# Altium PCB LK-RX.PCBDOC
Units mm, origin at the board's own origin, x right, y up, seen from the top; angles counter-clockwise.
Board outline 26.25 x 26.26 mm, 4 copper layers (Top Layer, MidLayer1, MidLayer2, Bottom Layer); 71 components, 48 nets, 217 pads, 64 vias.
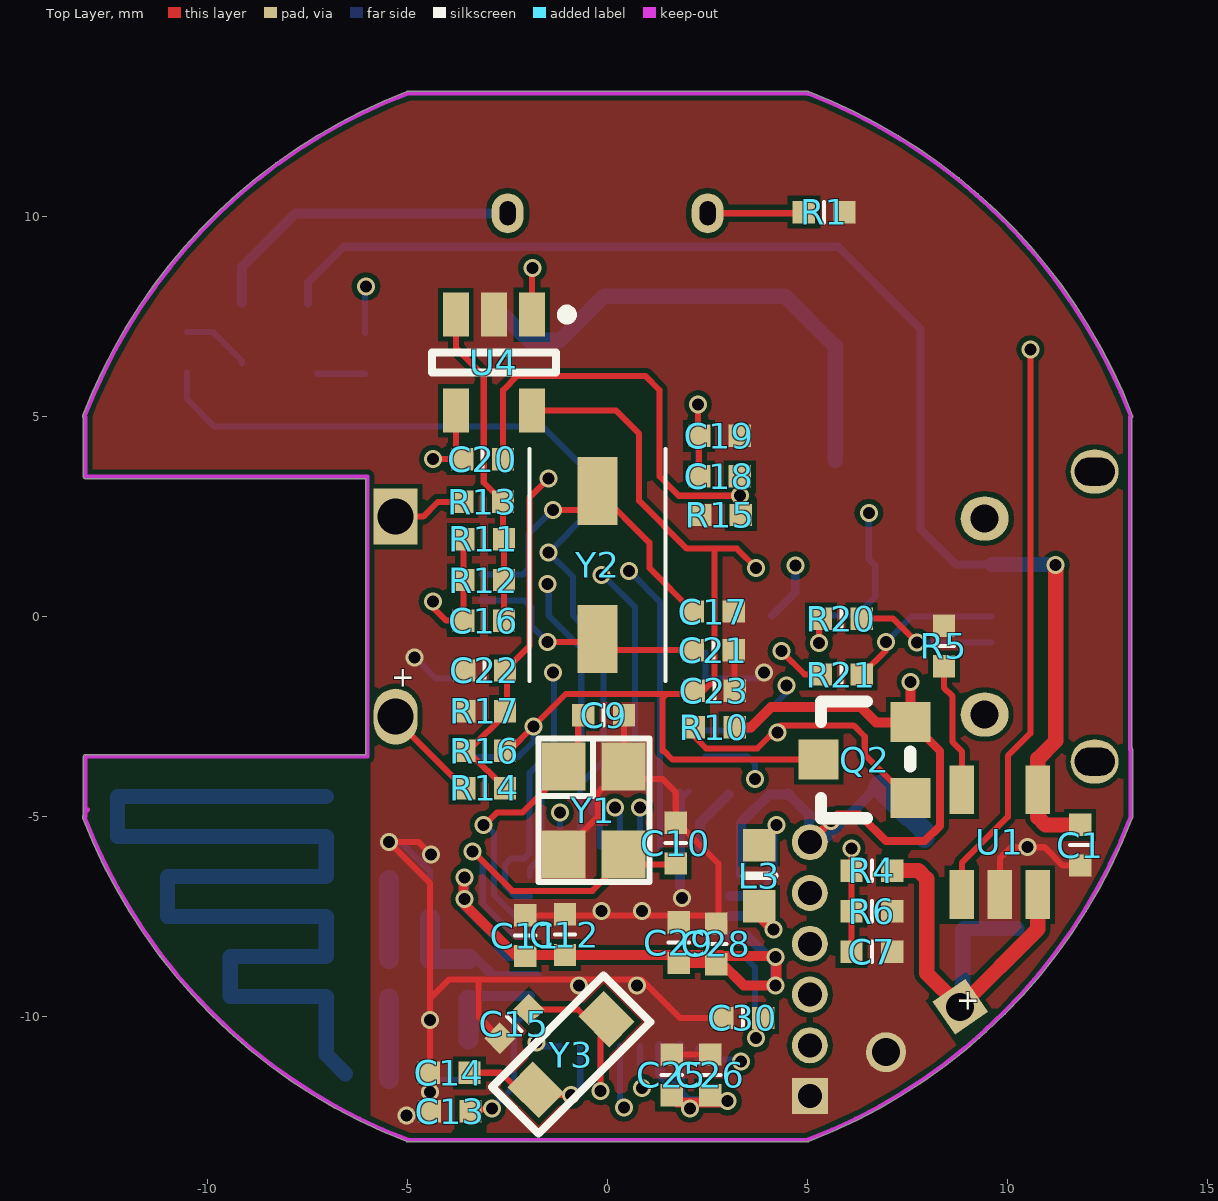
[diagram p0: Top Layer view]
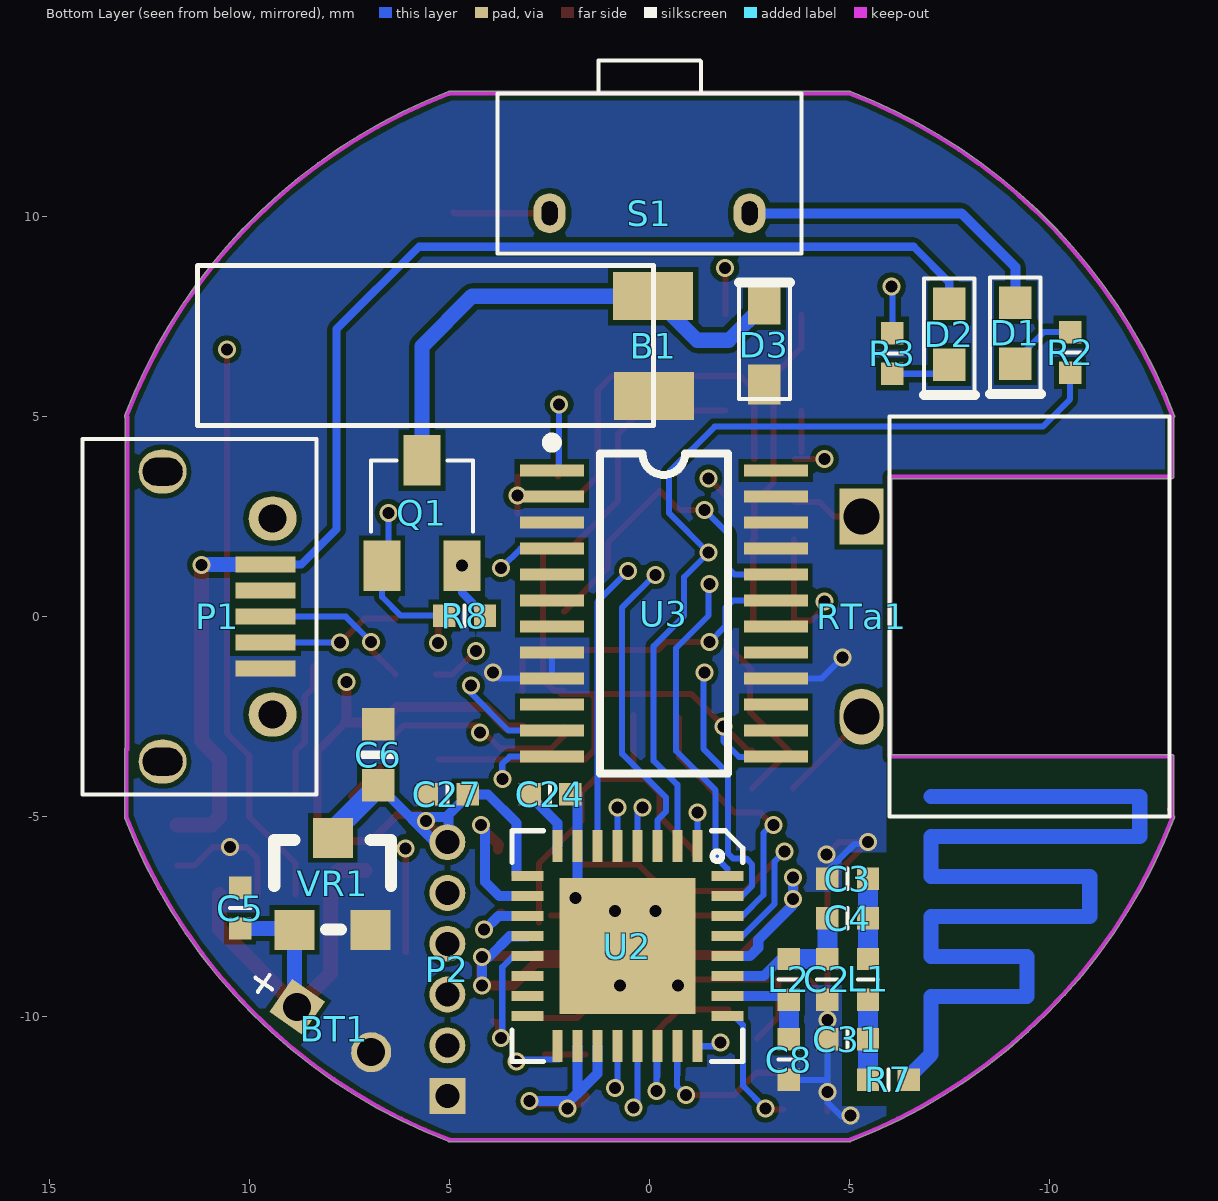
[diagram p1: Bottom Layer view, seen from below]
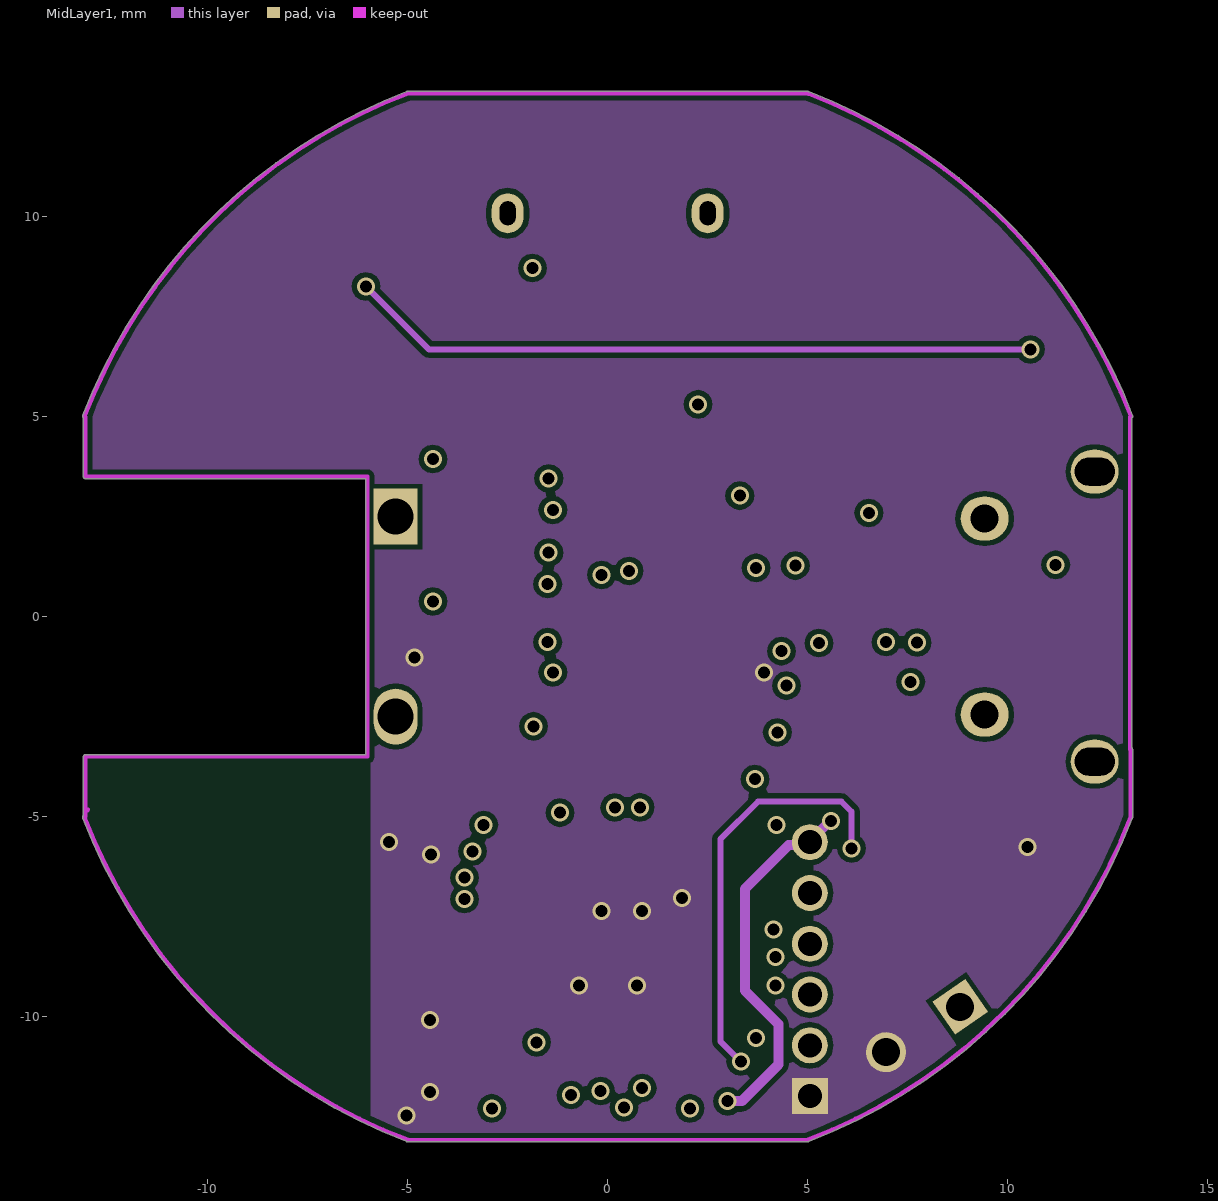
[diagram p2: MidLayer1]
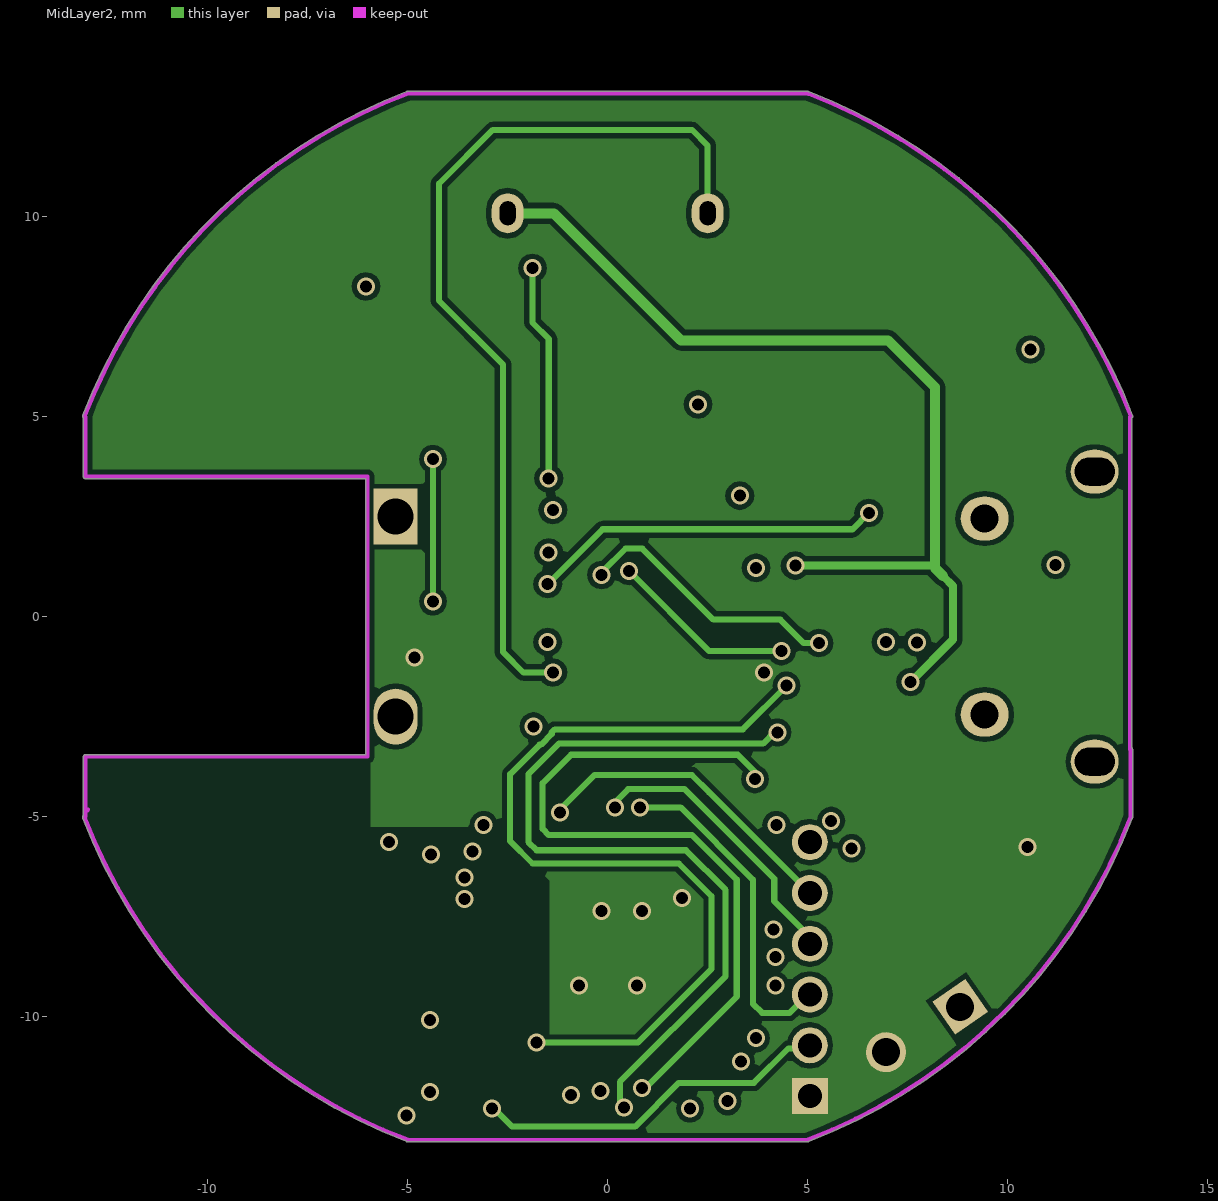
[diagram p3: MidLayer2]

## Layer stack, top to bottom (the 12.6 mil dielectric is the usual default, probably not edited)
Top Layer: signal copper 0.0356
Dielectric: prepreg 0.32, FR-4, Dk 4.8
MidLayer1: signal copper 0.0356
Dielectric: core 0.32, FR-4, Dk 4.8
MidLayer2: signal copper 0.0356
Dielectric: prepreg 0.32, FR-4, Dk 4.8
Bottom Layer: signal copper 0.0356

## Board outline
-13.118,-5.033 cw(c-13.071,-5.015) -13.119,-5.031 cw(c-13.073,-5.01) -13.108,-4.975 -13.106,-4.972 -13.106,-3.5 cw(c-13.056,-3.5) -13.056,-3.45 -6.05,-3.45 -6.05,3.45 -13.056,3.45 cw(c-13.056,3.5) -13.106,3.5 -13.106,4.968 cw(c-13.074,5.007) -13.121,5.025 cw(c0,0) -5.035,13.117 cw(c-5,13.081) -5,13.131 5,13.131 cw(c5,13.081) 5.035,13.117 cw(c0,0) 13.121,5.025 cw(c13.074,5.007) 13.124,5.007 cw(c13.074,5.007) 13.106,4.968 13.106,-3.281 cw(c13.071,-3.317) 13.121,-3.317 13.121,-5.015 cw(c13.071,-5.015) 13.118,-5.033 cw(c0,0) 5.033,-13.118 cw(c5,-13.08) 5,-13.13 -5,-13.13 cw(c-5,-13.08) -5.033,-13.118 cw(c0,0)

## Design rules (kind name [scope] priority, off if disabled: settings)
Clearance Clearance_1 [InNetClass('RF')] p1: gap=0.381
Clearance [All] p2: gap=0.127
ComponentClearance [All] p1: gap=0.127 collisioncheckmode=3 verticalgap=0.127 showdistances=FALSE
FabricationTestpoint [(IsPad And (OnTopLayer Or OnBottomLayer))] p1: side=3 testpointundercomponent=TRUE minsize=1.016 maxsize=2.54 preferedsize=1.524 minholesize=0 maxholesize=1.016 preferedholesize=0.813 testpointgrid=0.025 allowsidetop=TRUE allowsidebottom=TRUE usegrid=TRUE gridtolerance=0
PolygonConnect [All] p1: connectstyle=Direct reliefconductorwidth=0.254 reliefentries=4 polygonreliefangle="90 Angle"
RoutingCorners [All] p1: cornerstyle=Round minsetback=2.54 maxsetback=2.54
RoutingVias [All] p1: holewidth=0.305 width=0.508 viastyle="Through Hole" minholewidth=0.3 minwidth=0.45 maxholewidth=0.711 maxwidth=1.27
SilkscreenOverComponentPads SilkToSolderMaskClearance [IsPad] p1: minsilkscreentomaskgap=0.254
SolderMaskExpansion [All] p1: expansion=0.102
Width [All] p1: maxlimit=1 minlimit=0.152 preferedwidth=0.5
24 further rules are at their usual default settings.

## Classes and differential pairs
net class RF: NetC2_1 NetC3_2 NetE1_1 NetL1_1

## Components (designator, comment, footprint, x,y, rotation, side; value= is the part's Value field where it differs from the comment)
B1 "Motor" "MOTO-40*44*114 - 3D" -0.102,6.782 r90 bottom
BT1 "Battery" BT 8.814,-9.754 r215 bottom
C1 "1uF" 0402 11.811,-6.223 r90 top
C2 "1.2pF/10V" 0402 -4.445,-8.56 r270 bottom
C3 "1.8pF/10V" 0402 -4.445,-6.553 r180 bottom
C4 "220pF/10V" 0402 -5.461,-7.544 r0 bottom
C5 "1uF" 0402 10.236,-7.798 r90 bottom
C6 "22uF" 0603 6.782,-4.216 r90 bottom
C7 "100nF" 0402 7.112,-8.382 r180 top
C8 "18pF/10V" 0402 -3.48,-11.582 r90 bottom
C9 "12pF" 0402 -0.61,-2.464 r0 top
C10 "12pF" 0402 1.702,-6.172 r90 top
C11 "0.1uF/10V" 0402 -2.057,-7.468 r270 top
C12 "2.2uF/10V" 0402 -1.067,-7.442 r270 top
C13 "1uF/10V" 0402 -4.445,-12.37 r0 top
C14 "6pF" 0402 -4.47,-11.405 r0 top
C15 "6pF" 0402 -2.692,-10.541 r45 top
C16 "100pF" 0402 -3.607,-0.102 r0 top
C17 "15pF" 0402 2.134,0.127 r0 top
C18 "1nF" 0402 3.302,3.505 r180 top
C19 "10nF" 0402 2.286,4.521 r0 top
C20 "10nF" 0402 -3.632,3.937 r0 top
C21 "15pF" 0402 2.134,-0.838 r0 top
C22 "100pF" 0402 -3.581,-1.346 r0 top
C23 "0.1uF" 0402 3.175,-1.854 r180 top
C24 "1uF/10V" 0402 1.981,-4.445 r0 bottom
C25 "0.1uF/10V" 0402 1.6,-10.947 r270 top
C26 "1uF/10V" 0402 2.565,-10.947 r270 top
C27 "1uF/10V" 0402 5.563,-4.445 r180 bottom
C28 "1uF/10V" 0402 2.718,-7.671 r270 top
C29 "0.1uF/10V" 0402 1.778,-7.645 r270 top
C30 "1uF/10V" 0402 2.87,-10.033 r0 top
C31 "1.8pF/10V" 0402 -4.445,-10.566 r180 bottom (schematic designator C3)
D1 "LEDG" LED0603#1 -9.144,7.087 r270 bottom
D2 "LEDR" LED0603#1 -7.493,7.061 r270 bottom
D3 "IN4148" LED0603#2 -2.87,6.833 r90 bottom
L1 "1.8nH" 0402 -5.461,-9.576 r90 bottom
L2 "1.3nH" 0402 -3.48,-9.576 r90 bottom
L3 "47uH" 0603 3.785,-5.715 r270 top
P1 "microUSB" MICROUSB 9.6,0 r90 bottom
P2 "Header 6" SIP6-1.27 5.055,-11.989 r90 bottom
Q1 "AO3401A" AO3401 5.69,2.591 r180 bottom
Q2 "AO3401A" SOT23 6.426,-3.581 r90 top
R1 "10K" 0402 5.918,10.109 r180 top
R2 "1K" 0402 -10.516,6.096 r90 bottom
R3 "1K" 0402 -6.071,7.087 r270 bottom
R4 "2M" 0402 6.096,-6.35 r0 top
R5 "2K" 0402 8.407,-0.229 r270 top
R6 "200K" 0402 7.112,-7.366 r180 top
R7 "0" 0402 -6.477,-11.582 r0 bottom
R8 "10K" 0402 5.131,0.025 r180 bottom
R10 "10K" 0402 2.159,-2.769 r0 top
R11 "43K" 0402 -2.591,1.93 r180 top
R12 "43K" 0402 -2.591,0.914 r180 top
R13 "43K" 0402 -3.632,2.87 r0 top
R14 "43K" 0402 -3.581,-4.293 r0 top
R15 "2.7MR" 0402 2.311,2.54 r0 top
R16 "43K" 0402 -3.581,-3.353 r0 top
R17 "43K" 0402 -3.581,-2.362 r0 top
R20 "0R" 0402 5.334,-0.051 r0 top (schematic designator R5)
R21 "0R" 0402 5.334,-1.448 r0 top (schematic designator R5)
RTa1 "RX-40K" US-10MM -5,0 r180 bottom
S1 "开关" SW3x6x5 0,10.084 r0 bottom
U1 "TP4054" TP4054 9.804,-5.639 r0 top
U2 "TLSR8258F512ET32" QFN-32 -1.194,-5.74 r270 bottom
U3 "CS102" TSSOP24 -0.356,0.076 r90 bottom
U4 "LMV321" MF05A_N -2.845,6.35 r90 top
VR1 "MCP33" SOT23 7.925,-6.68 r180 bottom
Y1 "24M" XTAL4TN_3225 -0.356,-4.851 r270 top
Y2 "8M" 5032 -0.254,1.295 r270 top
Y3 "32.768K" S3215 -0.914,-10.947 r225 top

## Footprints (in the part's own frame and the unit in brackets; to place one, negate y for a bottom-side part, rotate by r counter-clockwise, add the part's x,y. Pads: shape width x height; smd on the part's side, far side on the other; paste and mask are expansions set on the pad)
0402 [mil]
  rect 22x22 smd: 1(0,0) 2(40,0)
  silkscreen extent 20,-10 20,10
0603 [mil]
  rect 32x32 smd: 1(0,0) 2(60,0)
  silkscreen extent 30,-15 30,15
5032 [mm]
  rect 1.7x1 smd: 1(-1.85,0) 2(1.85,0)
  silkscreen extent -2.9,-1.7 2.9,1.7
AO3401 [mm]
  rect 0.915x1.27 smd: 1(-1,-1.318) 2(1,-1.318) 3(0,1.318)
  silkscreen extent -1.27,-0.46 1.27,1.32
BT [mm]
  rect 1x1 hole 0.7: 1(0,0)
  round 1 hole 0.7: 2(2.172,0.133)
  silkscreen extent -1.27,-0.25 -0.76,0.25
LED0603#1 [mil]
  rect 32x32 smd: 1(-30,0) 2(30,0)
  silkscreen extent -55,-25 60,25
LED0603#2 [mil]
  rect 39.37x32 smd: 1(-40.65,0) 2(38.09,0)
  silkscreen extent -55,-25 60,25
MF05A_N [mm] "SOT23, 5-Leads, Body 2.9x1.6mm, Pitch 0.95mm, Lead Span 2.8mm, IPC Medium Density"
  rect 1.1x0.65 smd: 1(1.2,-0.95) 2(1.2,0) 3(1.2,0.95) 4(-1.2,0.95) 5(-1.2,-0.95)
  silkscreen extent -0.25,-1.95 1.32,1.55, body extent -0.9,-1.55 0.9,1.55, height 1.22
MICROUSB [mm]
  rect 0.4x1.5 smd: 1(-1.3,0) 2(-0.65,0) 3(0,0) 4(0.65,0) 5(1.3,0)
  oval 1.1x1.2 hole 0.7 slot 1 at 90 deg: ""(-3.625,2.575) ""(3.625,2.575)
  oval 1.1x1.2 hole 0.7: ""(-2.45,-0.175) ""(2.45,-0.175)
  silkscreen extent -4.44,-1.27 4.44,4.57
"MOTO-40*44*114 - 3D" [mm]
  rect 1.2x2 smd: 1(-1.263,-0.009) 2(1.228,0.012)
  silkscreen extent -2,0 2,11.4, body extent -2,0 1.99,10.55, height 3.4
QFN-32 [mm] "4*4/QFN40P"
  rect 0.8x0.25 smd: 1(0,0) 2(0,-0.5) 3(0,-1) 4(0,-1.5) 5(0,-2) 6(0,-2.5) 7(0,-3) 8(0,-3.5) 17(5,-3.5) 18(5,-3) 19(5,-2.5) 20(5,-2) 21(5,-1.5) 22(5,-1) 23(5,-0.5) 24(5,0)
  rect 0.25x0.8 smd: 9(0.75,-4.25) 10(1.25,-4.25) 11(1.75,-4.25) 12(2.25,-4.25) 13(2.75,-4.25) 14(3.25,-4.25) 15(3.75,-4.25) 16(4.25,-4.25) 25(4.25,0.75) 26(3.75,0.75) 27(3.25,0.75) 28(2.75,0.75) 29(2.25,0.75) 30(1.75,0.75) 31(1.25,0.75) 32(0.75,0.75)
  rect 3.4x3.4 smd: 33(2.5,-1.75)
  silkscreen extent -0.39,-4.64 5.39,1.14
S3215 [mm] "TFX-02S"
  rect 0.9x1.1 smd: 1(-1.25,0) 2(1.25,0)
  Top Layer pour cut-out: 0.575,0.65 0.575,-0.65 -0.575,-0.65 -0.575,0.65
  silkscreen extent -1.98,-0.82 1.98,0.82
SIP6-1.27 [mm]
  rect 0.9x0.9 hole 0.6: 1(0,0)
  round 0.9 hole 0.6: 2(1.27,0) 3(2.54,0) 4(3.81,0) 5(5.08,0) 6(6.35,0)
SOT23 [mm]
  rect 1x1 smd: 1(-0.953,-1.15) 2(0.953,-1.15) 3(0.005,1.15)
  silkscreen extent -1.46,-1.14 1.46,1.09
SW3x6x5 [mm]
  oval 0.8x1 hole 0.4 slot 0.6 at 90 deg: 1(-2.5,0) 2(2.5,0)
  silkscreen extent -3.8,-3.81 3.8,1
TP4054 [mm]
  rect 0.62x1.22 smd: 1(-0.95,-1.31) 2(0,-1.31) 3(0.95,-1.31) 4(0.95,1.31) 5(-0.95,1.31)
TSSOP24 [mm] "Shrink Small Outline; 24 Leads; Body Width 4.4 mm; Pitch 0.65 mm"
  rect 0.3x1.6 smd: 1(3.575,2.8) 2(2.925,2.8) 3(2.275,2.8) 4(1.625,2.8) 5(0.975,2.8) 6(0.325,2.8) 7(-0.325,2.8) 8(-0.975,2.8) 9(-1.625,2.8) 10(-2.275,2.8) 11(-2.925,2.8) 12(-3.575,2.8) 13(-3.575,-2.8) 14(-2.925,-2.8) 15(-2.275,-2.8) 16(-1.625,-2.8) 17(-0.975,-2.8) 18(-0.325,-2.8) 19(0.325,-2.8) 20(0.975,-2.8) 21(1.625,-2.8) 22(2.275,-2.8) 23(2.925,-2.8) 24(3.575,-2.8)
  silkscreen extent -4,-1.6 4.4,2.93
US-10MM [mm]
  oval 1.1x1.4 hole 0.9: +(0.3,-2.5)
  rect 1.1x1.4 hole 0.9: -(0.3,2.5)
  silkscreen extent 1,-5 8,5
XTAL4TN_3225 [mm]
  rect 1.2x1.1 smd: 1(-1.1,-0.75) 2(1.1,0.75) 3(1.1,-0.75) 4(-1.1,0.75)
  silkscreen extent -1.8,-1.38 1.79,1.4

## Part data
B1: "Motor, General Kind"
BT1: "Multicell Battery"
C1 C2 C3 C4 C5 C6 C7 C8 C9 C10 C11 C12 C13 C14 C15 C16 C17 C18 C19 C20 C21 C22 C23 C24 C25 C26 C27 C28 C29 C30 C31: library part Cap, "Capacitor"
D1 D2: library part LED0, "Typical INFRARED GaAs LED"
D3: library part Diode, "Default Diode"
L1 L2 L3: library part Inductor, "Inductor"
P1: library part "Header 5", "Header, 5-Pin"
P2: "Header, 6-Pin"
Q1 Q2: library part "AO3401A P道沟 X13A15 SOT-23", "MOS(场效应管)"
R1 R2 R3 R4 R5 R6 R7 R8 R10 R20 R21: library part Res1, "Resistor"
R11 R12 R13 R14 R15 R16 R17: library part Res2, "Resistor"
RTa1: library part TC40K
S1: library part SW-SPST, "Single-Pole, Single-Throw Switch"
U3: library part CS100
U4: library part LMV321M5, "General Purpose, Low Voltage, Rail-to-Rail Output Operational Amplifiers"
VR1: library part "Volt Reg", "Voltage Regulator"
Y1 Y2 Y3: library part XTAL, "Crystal Oscillator"

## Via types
v1: diameter 0.45, hole 0.3, Top Layer to Bottom Layer, tented both sides, 64 vias

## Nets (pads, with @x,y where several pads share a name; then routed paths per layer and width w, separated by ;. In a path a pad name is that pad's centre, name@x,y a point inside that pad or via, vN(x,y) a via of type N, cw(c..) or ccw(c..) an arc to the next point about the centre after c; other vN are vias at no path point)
1.2V: C11.2 C12.2 C28.2 C29.2 U2.12 U2.28 | length 17.7
  Top Layer w0.254: v1@-3.607,-6.553 -3.607,-7.163 -2.311,-8.458 C12.2 C28.2@2.845,-8.458 ; C29.2 2.845,-8.661 3.404,-9.22 4.216,-9.22 4.216,-8.534 4.166,-8.484 C28.2@2.54,-8.484 ; v1@4.191,-8.433 v1@4.293,-8.534
  Bottom Layer w0.254: v1@-3.581,-6.579 -3.581,-7.214 -2.718,-8.077 -2.718,-8.28 -2.515,-8.484 U2.28@-1.93,-8.484 ; U2.12 3.495,-7.99 v1@4.013,-8.509 ; v1@4.191,-9.271 v1(4.191,-8.509)
  other v1: 4.191,-9.22 -3.581,-7.061 -3.581,-6.528
+3.3V: C6.1 C25.2 C26.2 C27.2 D1.1 P2.6 Q1.2 Q2.2 R8.2 R10.2 S1.1 U2.9 U2.18 U2.19 VR1.3 | length 70.7
  Top Layer w0.203: P2.6 5.74,-4.953 6.299,-4.953 6.96,-5.613 7.925,-5.613 8.305,-5.233 8.305,-3.358 7.589,-2.642 Q2.2
  Top Layer w0.25: C25.2@1.6,-12.014 1.727,-12.141 2.972,-12.141 v1(2.997,-12.116) ; R10.2 3.581,-2.769 4.089,-2.261 6.325,-2.261 6.706,-2.642 7.589,-2.642 Q2.2@7.62,-2.642 ; Q2.2 v1(7.576,-1.633)
  MidLayer1 w0.25: v1(2.997,-12.116) 3.353,-12.116 4.267,-11.201 4.267,-10.185 3.429,-9.347 3.429,-6.807 4.521,-5.715 P2.6@5.055,-5.715 ; P2.6@5.218,-5.45 v1@5.595,-5.073
  MidLayer2 w0.203: v1(4.69,1.273) 8.125,1.273 ; v1(7.576,-1.633) 8.636,-0.573 8.636,0.762 8.388,1.01
  MidLayer2 w0.25: S1.1 -1.346,10.084 1.829,6.909 7.01,6.909 8.179,5.74 8.179,1.219 8.388,1.01
  Bottom Layer w0.203: R8.2 4.69,0.6 v1(4.69,1.273)
  Bottom Layer w0.25: D1.1 -9.144,8.738 -7.798,10.084 S1.1 ; U2.19 1.306,-11.43 1.806,-11.93 1.806,-11.915 ; 1.778,-11.887 1.806,-11.915 ; U2.18 1.806,-11.915 ; v1@2.007,-12.116 v1(2.997,-12.116) ; v1@2.032,-12.37 2.032,-12.141 1.806,-11.915 ; U2.9@3.327,-6.452 3.327,-5.156 4.039,-4.445 C27.2@4.521,-4.445 ; C27.2@4.496,-4.42 C27.2@4.521,-4.445 ; C27.2 C27.2@4.521,-4.445 ; P2.6@5.029,-5.588 5.029,-5.029 ; 5.029,-5.004 5.994,-5.004 ; 5.029,-4.953 C27.2@4.521,-4.445 ; P2.6@5.182,-5.613 5.385,-5.613 6.528,-4.47 C6.1@6.528,-4.445 ; C6.1@6.617,-4.28 VR1.3@7.442,-5.105
  Bottom Layer w0.508: C6.1 7.92,-5.354 VR1.3
  other v1: 2.057,-12.294 5.588,-5.105
+5V: C1.2 D2.1 P1.5 U1.4 | length 33.6
  Top Layer w0.381: v1(11.201,1.295) 11.201,-3.109 10.754,-3.556 U1.4 10.754,-5.014 10.947,-5.207 C1.2 C1.2@11.633,-5.207
  Bottom Layer w0.203: D2.1 -7.493,8.357 -6.604,9.246 5.766,9.246 7.823,7.188 7.823,2.184 8.708,1.3 P1.5
  Bottom Layer w0.381: P1.5 v1@11.197,1.3
ADC0: C7.2 R4.1 R6.2 U2.17 | length 14.5
  Top Layer w0.152: C7.2 R6.2 6.096,-6.528 v1(6.096,-5.791)
  MidLayer1 w0.152: v1(3.327,-11.125) 2.819,-10.617 2.819,-5.563 3.759,-4.623 5.359,-4.623 5.842,-4.623 6.096,-4.877 v1(6.096,-5.791)
  Bottom Layer w0.152: U2.17@2.261,-10.795 2.261,-11.074 3.277,-11.074 v1(3.327,-11.125) ; U2.17@2.306,-10.795 U2.17
CS102-EN: Q2.1 R10.1 U2.21 | length 29.2
  Top Layer w0.152: R10.1 2.159,-2.992 2.464,-3.297 3.739,-3.297 4.318,-2.718 6.147,-2.718 6.426,-2.997 6.426,-3.454 Q2.1@7.468,-4.496
  MidLayer2 w0.152: v1@0.306,-12.397 0.306,-11.632 2.946,-8.992 2.946,-6.833 1.956,-5.842 -1.778,-5.842 -1.981,-5.639 -1.981,-3.937 -1.219,-3.175 3.886,-3.175 v1@4.191,-2.87
  Bottom Layer w0.152: v1@0.306,-12.397 0.306,-11.176 ; 0.306,-11.431 0.306,-11.176 ; U2.21 0.306,-11.176
  other v1: 0.406,-12.268 4.242,-2.896
CS102-T: U2.20 U3.12 | length 21.6
  MidLayer2 w0.152: v1@0.813,-11.913 3.226,-9.5 3.226,-6.576 2.111,-5.461 -1.473,-5.461 -1.626,-5.309 -1.626,-4.166 -0.914,-3.454 3.251,-3.454 v1@3.759,-3.962
  Bottom Layer w0.152: U2.20 0.806,-11.906 v1@0.813,-11.913 ; U3.12 3.499,-3.499 3.683,-3.683 v1(3.683,-4.064)
  other v1: 0.864,-11.786
ECHO: U2.24 U3.11 | length 25.1
  MidLayer2 w0.152: v1(-1.778,-10.643) 0.762,-10.643 2.591,-8.814 2.591,-6.985 1.778,-6.172 -1.88,-6.172 -2.438,-5.613 -2.438,-3.937 -1.702,-3.2 ; -1.665,-3.2 -1.397,-2.933 ; -1.397,-2.896 -1.321,-2.819 3.378,-2.819 v1(4.47,-1.727)
  Bottom Layer w0.152: v1@-1.731,-10.74 U2.24 ; U3.11 3.527,-2.849 4.47,-1.905 v1(4.47,-1.727)
GND: B1.1 BT1.2 C1.1 C2.2 C3.1 C5.2 C6.2 C7.1 C8.1 C9.2 C10.2 C11.1 C12.1 C13.1 C14.1 C15.1 C17.2 C19.2 C21.2 C22.1 C23.1 C24.1 C25.1 C26.1 C27.1 C28.1 C29.1 C30.1 C31.1 D3.1 P1.1 P2.1 R1.1 R5.1 R6.1 R15.1 R17.1 U1.2 U2.7 U2.33 U3.3 U3.8 U3.9 U3.16 U3.21 U3.22 U3.23 U4.2 VR1.2 Y1.3 Y1.4 | length 49.2
  Top Layer w0.152: C13.1 v1(-4.445,-11.887) v1(-4.445,-10.084) -4.445,-9.55 ; v1(-4.42,-5.944) -4.724,-5.639 v1(-5.461,-5.639) -4.445,-6.655 -4.445,-9.55 ; C15.1 -3.226,-10.008 -3.226,-9.068 ; C11.1 C28.1@2.464,-7.468 ; Y1.3 -1.106,-5.855 -0.25,-5 -0.25,-4.416 0.102,-4.064 1.372,-4.064 1.702,-4.394 1.702,-5.105 2.769,-6.172 C28.1@2.769,-7.645 ; Y1.4 0.406,-3.739 C9.2 ; C25.1 C26.1 C26.1@2.616,-10.947 ; C30.1 1.803,-10.033 0.838,-9.068 -3.226,-9.068 ; C21.2 3.175,-0.864 C23.1 ; U1.2 9.804,-6.045 10.084,-5.766 10.922,-5.766 11.379,-6.223 C1.1 ; -4.445,-9.55 -3.962,-9.068 -3.226,-9.068
  Bottom Layer w0.152: v1(-5.461,-5.639) -5.41,-5.69 -5.119,-5.69 -4.445,-6.364 C3.1 ; v1@-4.978,-12.497 -4.801,-12.497 -4.445,-12.141 C2.2 ; v1(-4.826,-1.016) -4.293,-1.549 U3.16 ; -4.369,-11.582 C8.1 ; U2.7 U2.7@1.829,-5.718 ; C24.1@1.829,-4.572 C24.1@2.032,-4.369 ; U3.8 U3.9 3.76,-1.549 v1(3.912,-1.397)
  Bottom Layer w0.25: U2.33@1.803,-6.731 C24.1@1.803,-4.42
  other v1: -5.029,-12.471 -0.711,-9.22 0.737,-9.22 -0.152,-7.366 0.864,-7.366 1.854,-7.036 10.49,-5.766
LED: R2.1 U2.2 | length 22.9
  Bottom Layer w0.152: R2.1 -10.516,5.436 -9.83,4.75 -1.626,4.75 -0.483,3.607 -0.483,2.591 v1(-1.473,1.6) -0.864,0.991 -0.864,0.025 -0.102,-0.737 -0.102,-1.88 ; U2.2 -0.694,-4.199 -0.102,-3.607 -0.102,-1.88 ; -0.102,-1.041 -0.102,-1.88
M-EN: Q1.1 R8.1 U2.32 | length 23
  MidLayer2 w0.152: v1(-1.499,0.813) -0.127,2.184 4.039,2.184 ; 4.369,2.184 4.039,2.184 ; v1(6.528,2.591) 6.121,2.184 4.039,2.184
  Bottom Layer w0.152: U2.32 -1.944,-6.301 -1.651,-6.009 -1.651,-4.343 -0.66,-3.353 -0.66,-2.921 ; v1@-1.473,0.838 -1.473,0.025 -0.66,-0.787 -0.66,-2.921 ; -0.66,-1.118 -0.66,-2.921 ; R8.1 6.223,0.025 6.69,0.492 Q1.1 6.528,1.435 v1(6.528,2.591)
NetB1_2: B1.2 D3.2 Q1.3 | length 12.8
  Bottom Layer w0.381: D3.2 -1.979,6.909 -1.191,6.909 B1.2 4.436,8.01 5.69,6.756 Q1.3
NetC2_1: C2.1 C4.2 L2.2 U2.27 | length 3.9
  Bottom Layer w0.25: L2.2@-3.505,-8.585 -3.251,-8.585 -2.846,-8.99 U2.27@-1.766,-8.99
  Bottom Layer w0.5: C4.2 C2.1 L2.2@-3.454,-8.56
NetC3_2: C3.2 C4.1 L1.2 | length 2
  Bottom Layer w0.5: L1.2 C3.2@-5.461,-6.579
NetC8_2: C8.2 L2.1 U2.26 | length 2.5
  Bottom Layer w0.25: L2.1@-3.489,-9.49 U2.26
  Bottom Layer w0.5: C8.2 L2.1
NetC9_1: C9.1 U2.30 Y1.1 | length 7.1
  Top Layer w0.152: v1@-3.073,-5.207 -2.769,-4.902 -2.134,-4.902 -0.737,-3.505 C9.1@-0.737,-2.54
  Bottom Layer w0.152: v1@-3.175,-5.08 -2.845,-5.41 -2.845,-6.96 -2.314,-7.49 U2.30
  other v1: -3.099,-5.207
NetC10_1: C10.1 U2.29 Y1.2 | length 8.7
  Top Layer w0.152: v1(-3.378,-5.867) -2.388,-6.858 -0.381,-6.858 0.279,-6.198 C10.1@1.676,-6.198
  Bottom Layer w0.152: v1(-3.378,-5.867) -3.124,-6.121 -3.124,-7.075 -3.124,-7.178 -2.312,-7.99 U2.29
NetC14_2: C14.2 U2.23 Y3.2 | length 4.8
  Top Layer w0.152: C14.2 -2.667,-11.405 -2.108,-11.963 v1(-0.914,-11.963)
  Bottom Layer w0.152: v1(-0.914,-11.963) -0.686,-11.735 U2.23@-0.686,-10.719 ; -0.694,-11.463 U2.23
NetC15_2: C15.2 U2.22 Y3.1 | length 5.6
  Top Layer w0.152: C15.2 -0.744,-9.823 Y3.1@-0.483,-10.084 ; Y3.1@-0.47,-10.071 -0.178,-10.363 v1(-0.178,-11.862)
  Bottom Layer w0.152: -0.194,-11.49 U2.22 ; v1(-0.178,-11.862) U2.22@-0.178,-10.566
NetC16_1: C16.1 C20.1 R11.2 R12.2 U4.4 | length 8.5
  Top Layer w0.152: v1(-4.369,0.381) -4.369,0.229 -4.039,-0.102 C16.1 ; v1(-4.369,3.937) C20.1 ; C20.1@-3.795,4.1 U4.4 ; C16.1@-3.607,-0.178 C16.1 ; R11.2 R12.2 C16.1
  MidLayer2 w0.152: v1(-4.369,0.381) v1(-4.369,3.937)
NetC16_2: C16.2 R11.1 R12.1 R13.2 U4.3 | length 8.1
  Top Layer w0.152: U4.3 -3.795,6.716 -3.099,6.02 -3.099,3.353 R13.2 -2.616,2.007 R11.1@-2.642,1.981 ; C16.2 R12.1 R11.1
NetC17_1: C17.1 U3.20 Y2.1 | length 8.3
  Top Layer w0.152: v1(-1.372,2.667) -0.732,2.667 Y2.1 1.041,1.85 1.041,1.219 C17.1
  Bottom Layer w0.152: U3.20 -2.124,1.051 -1.981,1.194 -1.981,2.057 v1(-1.372,2.667)
NetC21_1: C21.1 U3.19 Y2.2 | length 6
  Top Layer w0.152: v1(-1.499,-0.635) Y2.2@-0.406,-0.635 ; Y2.2@-0.356,-0.686 -0.203,-0.838 C21.1
  Bottom Layer w0.152: U3.19 -2.078,0.401 -1.905,0.229 -1.905,-0.229 v1(-1.499,-0.635)
NetC22_2: C22.2 R14.2 R16.1 R17.2 U4.1 | length 15.7
  Top Layer w0.152: R14.2 -3.48,-3.378 -3.48,-3.353 -2.515,-2.388 C22.2@-2.515,-1.295 ; C22.2 C22.2@-2.515,-1.295 ; C22.2@-2.489,-1.27 C22.2@-2.515,-1.295 ; U4.1 -1.895,8.697 v1(-1.88,8.712) ; v1(-1.473,3.454) -1.956,2.972 -1.956,-0.737 C22.2@-2.515,-1.295
  MidLayer2 w0.152: v1(-1.88,8.712) -1.88,7.352 -1.473,6.945 v1(-1.473,3.454)
NetC24_2: C24.2 U2.8 | length 1.7
  Bottom Layer w0.25: U2.8 2.306,-5.161 C24.2@3.023,-4.445 ; U2.8@2.311,-5.893 U2.8@2.311,-5.74
NetC30_2: C30.2 U2.13 | length 3
  Top Layer w0.152: v1@3.785,-10.643 C30.2@3.785,-10.135 ; C30.2@3.861,-10.16 C30.2@3.912,-10.109
  Bottom Layer w0.152: U2.13 3.41,-8.49 3.683,-8.763 v1@3.683,-10.49
  other v1: 3.708,-10.541
NetD1_2: D1.2 R2.2 | length 1.7
  Bottom Layer w0.152: R2.2 -9.855,7.112 -9.144,6.401 D1.2
NetD2_2: D2.2 R3.2 | length 1.2
  Bottom Layer w0.152: D2.2@-7.264,6.071 R3.2
NetE1_1: R7.1 | length 30.3
  Bottom Layer w0.381: -7.036,-4.497 -12.252,-4.497 -12.252,-5.498 -7.036,-5.498 -7.036,-6.498 -11.007,-6.498 -11.007,-7.499 -7.036,-7.499 -7.036,-8.499 -9.433,-8.499 -9.433,-9.5 -7.036,-9.5 -7.036,-10.947 R7.1@-6.553,-11.43
NetL1_1: C31.2 L1.1 R7.2 | length 2
  Bottom Layer w0.5: R7.2@-5.461,-11.557 C31.2 L1.1@-5.461,-9.55
NetL3_1: L3.1 U2.10 | length 3.6
  Top Layer w0.25: L3.1@3.759,-5.715 v1@4.293,-5.182 ; L3.1@3.785,-5.817 L3.1@3.785,-5.664
  Bottom Layer w0.25: U2.10 3.754,-6.99 4.115,-6.629 4.115,-5.334 v1@4.267,-5.182
  other v1: 4.216,-5.207
NetL3_2: L3.2 U2.11 | length 1.8
  Top Layer w0.25: L3.2@3.708,-7.417 v1@4.14,-7.849
  Bottom Layer w0.25: U2.11 3.782,-7.49 v1@4.14,-7.849
  other v1: 4.14,-7.823
NetP1_2: P1.2 R20.2 | length 3.5
  Top Layer w0.152: R20.2 7.137,-0.051 v1(7.737,-0.65)
  Bottom Layer w0.152: v1(7.737,-0.65) P1.2
NetP1_3: P1.3 R21.2 | length 4
  Top Layer w0.152: R21.2 6.96,-0.838 v1(6.96,-0.635)
  Bottom Layer w0.152: v1(6.96,-0.635) 7.595,0 P1.3
NetR3_1: R3.1 U1.1 | length 32.7
  Top Layer w0.152: U1.1 8.854,-6.157 10.008,-5.004 10.008,-3.48 10.566,-2.921 v1(10.566,6.68)
  MidLayer1 w0.152: v1(-6.045,8.255) -4.47,6.68 v1(10.566,6.68)
  Bottom Layer w0.152: R3.1 v1@-6.071,8.23
NetR5_2: R5.2 U1.5 | length 3.3
  Top Layer w0.152: R5.2 8.407,-1.778 8.622,-1.992 8.622,-3.135 8.854,-3.368 U1.5
NetR13_1: R13.1 RTa1.- | length 1.8
  Top Layer w0.152: RTa1.- -4.612,2.5 -4.242,2.87 R13.1
NetR14_1: R14.1 RTa1.+ | length 2.3
  Top Layer w0.152: RTa1.+@-5.182,-2.692 R14.1
RESET: C13.2 P2.2 U2.25 | length 12.2
  Top Layer w0.152: C13.2@-3.353,-12.319 -2.921,-12.319 v1(-2.896,-12.294)
  MidLayer2 w0.152: v1@-2.87,-12.268 -2.388,-12.751 0.686,-12.751 1.778,-11.659 3.658,-11.659 4.521,-10.795 P2.2@5.004,-10.795
  Bottom Layer w0.152: v1(-2.896,-12.294) -2.337,-11.735 -2.337,-10.211 -2.116,-9.99 U2.25
RN: C18.2 C19.1 U3.1 | length 3.3
  Top Layer w0.152: C19.1@2.261,4.547 v1(2.261,5.309) ; C18.2 C19.1
  Bottom Layer w0.152: 2.261,3.835 v1(2.261,5.309)
RP: C18.1 C20.2 R15.2 U3.2 | length 11.2
  Top Layer w0.152: C20.2 -2.616,5.664 -2.261,6.02 0.94,6.02 1.295,5.664 1.295,3.505 1.778,3.023 v1(3.302,3.023) ; R15.2@3.302,2.565 v1(3.302,3.023) ; C18.1 v1(3.302,3.023)
RX: R20.1 U2.3 | length 15.2
  Top Layer w0.152: v1(5.283,-0.66) 5.283,-0.102 R20.1
  MidLayer2 w0.152: v1(-0.152,1.041) -0.152,1.104 0.446,1.702 0.864,1.702 2.642,-0.076 4.318,-0.076 4.902,-0.66 v1(5.283,-0.66)
  Bottom Layer w0.152: U2.3 -0.194,-5.089 -0.414,-4.869 -0.414,-4.529 0.686,-3.429 0.686,-0.991 ; v1@-0.051,0.965 0.686,0.229 0.686,-0.991 ; 0.686,-0.686 0.686,-0.991
SWM: P2.5 U2.1 | length 8.8
  MidLayer2 w0.152: v1(-1.194,-4.902) -1.194,-4.826 -0.33,-3.962 2.108,-3.962 2.54,-4.394 P2.5 ; P2.5@5.105,-6.934 P2.5@5.105,-6.909
  Bottom Layer w0.152: U2.1 v1(-1.194,-4.902)
SWS: P2.3 U2.5 | length 9.4
  MidLayer2 w0.152: v1(0.806,-4.769) 1.822,-4.769 3.632,-6.579 3.632,-9.677 3.861,-9.906 4.547,-9.906 P2.3@5.055,-9.398
  Bottom Layer w0.152: U2.5 v1(0.806,-4.769)
TP: P2.4 U2.4 | length 8.3
  MidLayer2 w0.152: v1@0.102,-4.724 0.515,-4.311 0.914,-4.311 1.924,-4.311 4.166,-6.553 4.166,-7.112 5.182,-8.128 P2.4@5.182,-8.255 ; v1(0.178,-4.775) v1@0.178,-4.724
  Bottom Layer w0.152: U2.4 v1@0.306,-4.775
TX: R21.1 U2.6 | length 13
  Top Layer w0.152: v1(4.343,-0.864) 4.928,-1.448 R21.1
  MidLayer2 w0.152: v1(0.533,1.143) 2.54,-0.864 v1(4.343,-0.864)
  Bottom Layer w0.152: v1@0.584,1.092 1.306,0.37 U2.6
VBAT: BT1.1 C5.1 R4.2 U1.3 VR1.1 | length 11.4
  Top Layer w0.381: R4.2 7.772,-6.35 7.976,-6.553 7.976,-8.915 BT1.1 10.754,-7.813 U1.3
  Bottom Layer w0.381: BT1.1 8.877,-9.69 VR1.1 ; VR1.1@8.91,-7.798 C5.1
VCC-CS102: C23.2 Q2.3 R16.2 U3.4 U3.13 U4.5 | length 26.3
  Top Layer w0.152: R16.2 -2.464,-3.353 v1(-1.854,-2.743) -1.041,-1.93 1.473,-1.93 ; U4.5 0.209,5.15 0.787,4.572 0.787,2.896 1.981,1.702 3.226,1.702 v1(3.708,1.219) ; 1.372,-3.353 1.372,-2.032 1.473,-1.93 ; 1.397,-3.353 1.621,-3.576 Q2.3 ; C23.2@2.146,-1.867 C23.2 2.388,-1.854 2.667,-1.575 2.667,1.676 ; C23.2@2.21,-1.93 1.473,-1.93
  Bottom Layer w0.152: U3.13@-3.251,-3.505 -2.235,-3.505 -1.854,-3.124 v1(-1.854,-2.743) ; U3.4 3.226,1.701 v1(3.708,1.219)
WKUP: R1.2 S1.2 U2.31 | length 32.2
  Top Layer w0.152: S1.2 4.877,10.084 R1.2
  MidLayer2 w0.152: v1(-1.372,-1.397) -2.108,-1.397 -2.616,-0.889 -2.616,6.299 -4.216,7.899 -4.216,10.82 -2.87,12.167 2.108,12.167 2.5,11.775 S1.2
  Bottom Layer w0.152: U2.31 -2.306,-6.99 -2.565,-6.731 -2.565,-6.198 -2.413,-6.045 -2.083,-6.045 -1.956,-5.918 -1.956,-3.912 -1.346,-3.302 v1@-1.346,-1.372
pads on no net: P1. P1.4 U2.14 U2.15 U2.16 U3.5 U3.6 U3.7 U3.10 U3.14 U3.15 U3.17 U3.18 U3.24

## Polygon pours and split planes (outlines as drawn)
GND on Top Layer "MidLayer1-No Net" (solid, remove dead copper, pour order 1003): -13.208,15.85 -11.633,14.275 17.018,14.275 17.018,-5.918 9.423,-13.513 -5.918,-13.513 -5.918,-1.524 -10.033,2.591 -14.986,2.591 -14.986,14.072
GND on Bottom Layer "MidLayer1-No Net" (solid, remove dead copper, pour order 1002): -13.208,15.85 -11.633,14.275 17.018,14.275 17.018,-5.918 9.423,-13.513 -5.918,-13.513 -5.918,-1.524 -10.033,2.591 -14.986,2.591 -14.986,14.072
GND on MidLayer2 "MidLayer1-No Net" (solid, remove dead copper, pour order 1000): -13.208,15.85 -11.633,14.275 17.018,14.275 17.018,-5.918 16.637,-6.299 9.423,-13.513 7.137,-13.513 -0.33,-13.513 -0.533,-13.716 -0.787,-13.97 -0.787,-14.021 -1.27,-14.021 -1.321,-13.97 -1.448,-13.843 -1.448,-9.068 -1.448,-6.604 -2.05,-6.001 -2.794,-5.258 -5.918,-5.258 -5.918,-1.524 -8.611,1.168 -10.033,2.591 -14.986,2.591 -14.986,14.072 -13.208,15.85
GND on MidLayer1 "MidLayer1-No Net" (solid, remove dead copper, pour order 1001): -13.208,15.85 -11.633,14.275 17.018,14.275 17.018,-5.918 9.423,-13.513 -5.918,-13.513 -5.918,-1.524 -10.033,2.591 -14.986,2.591 -14.986,14.072

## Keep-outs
Keep-Out Layer:
  lines w0.1: -13.074,5.007 cw(c0,0) -4.99,13.081 ; -13.073,-5.01 -13.056,-4.993 -13.056,-3.5 -6,-3.5 -6,3.5 -13.056,3.5 -13.056,4.989 ; -13.071,-5.015 ccw(c0,0) -5.007,-13.074 ; -13.005,-4.841 -12.988,-4.824 ; -5,-13.08 5,-13.08 ; -5,13.081 5,13.081 ; 5.007,-13.074 ccw(c0,0) 13.071,-5.015 13.071,-3.317 ; 5.015,13.071 cw(c0,0) 13.074,5.007 ; 13.056,-3.317 13.056,3.302 13.056,4.989

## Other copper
Bottom Layer:
  pour cut-out: 1.321,-5.029 1.321,-6.248 2.159,-6.248 2.159,-5.029
  pour cut-out: -1.397,-6.274 -1.397,-10.211 2.54,-10.211 2.54,-6.274

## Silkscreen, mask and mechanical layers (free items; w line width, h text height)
Top Overlay:
  text "+" at -5.41,-1.753 h0.51
  text "+" at 8.712,-9.83 h0.51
